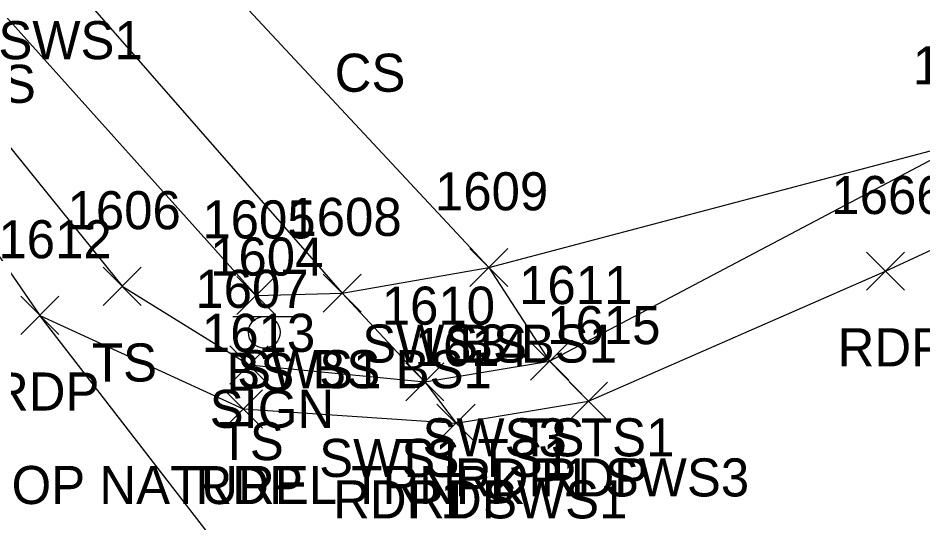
# Model space of a CAD drawing. Extents: x 1499292 to 1501024, y 534584 to 538043.
# Drawn here: x 1499887.83 to 1499935.33, y 537602.65 to 537629.17 of the extents above; entities that cross this region are included whole.
import ezdxf

# ---------------------------------------------------------------- set-up
doc = ezdxf.new("R2010")
doc.units = 0
for name, color, linetype in [('L_A', 7, 'Continuous'), ('L_I', 7, 'Continuous'), ('L_TIC', 7, 'Continuous'), ('LELB', 7, 'Continuous'), ('P_A', 7, 'Continuous'), ('P_I', 7, 'Continuous'), ('P_TIC', 7, 'Continuous'), ('PET', 7, 'Continuous'), ('R_A', 7, 'Continuous'), ('R_I', 7, 'Continuous'), ('R_TIC', 7, 'Continuous'), ('RSW', 7, 'Continuous'), ('S_A', 7, 'Continuous'), ('S_C', 7, 'Continuous'), ('S_I', 7, 'Continuous'), ('SSGN', 7, 'Continuous')]:
    doc.layers.add(name, color=color, linetype=linetype)

msp = doc.modelspace()

# ---------------------------------------------------------------- linework, layer by layer
at = {"layer": 'L_TIC'}
for points in [[(1499911.539, 537615.07), (1499913.539, 537617.07)], [(1499913.539, 537615.07), (1499911.539, 537617.07)], [(1499892.294, 537614.077), (1499894.294, 537616.077)], [(1499894.294, 537614.077), (1499892.294, 537616.077)], [(1499899.318, 537613.592), (1499901.318, 537615.592)], [(1499901.318, 537613.592), (1499899.318, 537615.592)], [(1499903.837, 537613.724), (1499905.837, 537615.724)], [(1499905.837, 537613.724), (1499903.837, 537615.724)], [(1499898.95, 537609.946), (1499900.95, 537611.946)], [(1499900.95, 537609.946), (1499898.95, 537611.946)], [(1499914.735, 537610.144), (1499916.735, 537612.144)], [(1499916.735, 537610.144), (1499914.735, 537612.144)], [(1499908.177, 537609.062), (1499910.177, 537611.062)], [(1499910.177, 537609.062), (1499908.177, 537611.062)]]:
    msp.add_lwpolyline(points, dxfattribs=at)
at = {"layer": 'LELB'}
for points in [[(1499875.628, 537635.389), (1499883.617, 537627.063), (1499893.294, 537615.077), (1499899.95, 537610.946), (1499909.177, 537610.062), (1499915.735, 537611.144), (1499937.582, 537622.682), (1499960.484, 537631.227), (1499993.025, 537642.588), (1500017.771, 537650.353)], [(1499878.067, 537642.108), (1499886.752, 537629.716), (1499900.318, 537614.592), (1499904.837, 537614.724), (1499912.539, 537616.07), (1499937.582, 537622.682)]]:
    msp.add_lwpolyline(points, dxfattribs=at)
at = {"layer": 'P_TIC'}
for points in [[(1499932.365, 537614.874), (1499934.365, 537616.874)], [(1499934.365, 537614.874), (1499932.365, 537616.874)], [(1499887.962, 537612.552), (1499889.962, 537614.552)], [(1499889.962, 537612.552), (1499887.962, 537614.552)], [(1499887.962, 537612.552), (1499889.962, 537614.552)], [(1499889.962, 537612.552), (1499887.962, 537614.552)], [(1499916.779, 537608.039), (1499918.779, 537610.039)], [(1499918.779, 537608.039), (1499916.779, 537610.039)], [(1499898.651, 537607.634), (1499900.651, 537609.634)], [(1499900.651, 537607.634), (1499898.651, 537609.634)], [(1499909.819, 537606.885), (1499911.819, 537608.885)], [(1499911.819, 537606.885), (1499909.819, 537608.885)]]:
    msp.add_lwpolyline(points, dxfattribs=at)
at = {"layer": 'PET'}
for points in [[(1499877.015, 537630.958), (1499888.962, 537613.552), (1499899.651, 537608.634), (1499910.819, 537607.885), (1499917.779, 537609.039), (1499933.365, 537615.874), (1499940.692, 537619.272), (1499961.056, 537627.699), (1499994.297, 537637.632), (1500011.746, 537642.235), (1500032.99, 537648.112)], [(1500289.781, 537338.292), (1500253.04, 537372.984), (1500224.755, 537395.044), (1500200.638, 537412.645), (1500169.786, 537433.283), (1500131.366, 537455.397), (1500082.939, 537477.86), (1500052.71, 537490.83), (1500028.687, 537501.079), (1500007.589, 537509.927), (1499989.795, 537518.651), (1499972.477, 537528.523), (1499952.084, 537542.885), (1499935.462, 537557.311), (1499909.986, 537586.349), (1499888.962, 537613.552)]]:
    msp.add_lwpolyline(points, dxfattribs=at)
at = {"layer": 'R_TIC'}
for points in [[(1499911.539, 537615.07), (1499913.539, 537617.07)], [(1499913.539, 537615.07), (1499911.539, 537617.07)], [(1499903.837, 537613.724), (1499905.837, 537615.724)], [(1499905.837, 537613.724), (1499903.837, 537615.724)], [(1499914.735, 537610.144), (1499916.735, 537612.144)], [(1499916.735, 537610.144), (1499914.735, 537612.144)], [(1499908.177, 537609.062), (1499910.177, 537611.062)], [(1499910.177, 537609.062), (1499908.177, 537611.062)], [(1499916.779, 537608.039), (1499918.779, 537610.039)], [(1499918.779, 537608.039), (1499916.779, 537610.039)], [(1499909.819, 537606.885), (1499911.819, 537608.885)], [(1499911.819, 537606.885), (1499909.819, 537608.885)]]:
    msp.add_lwpolyline(points, dxfattribs=at)
at = {"layer": 'RSW'}
for points in [[(1499852.884, 537673.411), (1499857.278, 537677.521), (1499874.596, 537657.81), (1499894.119, 537635.847), (1499912.539, 537616.07), (1499915.735, 537611.144), (1499917.779, 537609.039)], [(1499852.884, 537673.411), (1499870.266, 537654.325), (1499889.752, 537632.008), (1499904.837, 537614.724), (1499909.177, 537610.062), (1499910.819, 537607.885)]]:
    msp.add_lwpolyline(points, dxfattribs=at)
at = {"layer": 'SSGN'}
for p, q in [((1499899.101, 537613.494), (1499902.434, 537613.494)), ((1499900.748, 537612.661), (1499900.748, 537612.661))]:
    msp.add_line(p, q, dxfattribs=at)
msp.add_circle((1499900.748, 537612.661), 0.833, dxfattribs=at)

# ---------------------------------------------------------------- texts
at = {"layer": 'L_A'}
for s, p in [('CS', (1499904.446, 537625.298)), ('BS', (1499885.193, 537624.716)), ('BS', (1499910.98, 537611.07)), ('TS', (1499891.703, 537610.077)), ('BS', (1499898.759, 537609.592)), ('BS', (1499903.278, 537609.724)), ('TS', (1499914.145, 537606.144)), ('TS', (1499898.359, 537605.946)), ('TS', (1499907.586, 537605.062))]:
    msp.add_text(s, height=2, dxfattribs=at).set_placement(p)
at = {"layer": 'L_I'}
for s, p in [('1667', (1499934.794, 537625.682)), ('1667', (1499934.794, 537625.682)), ('1609', (1499909.712, 537619.07)), ('1606', (1499890.42, 537618.077)), ('1605', (1499897.499, 537617.592)), ('1608', (1499902.019, 537617.724)), ('1611', (1499914.129, 537614.144)), ('1607', (1499897.131, 537613.946)), ('1610', (1499906.917, 537613.062))]:
    msp.add_text(s, height=2, dxfattribs=at).set_placement(p)
at = {"layer": 'P_A'}
for p in [(1499930.853, 537610.874), (1499886.451, 537608.552), (1499886.451, 537608.552), (1499897.139, 537603.634), (1499915.267, 537604.039), (1499908.307, 537602.885)]:
    msp.add_text('RDP', height=2, dxfattribs=at).set_placement(p)
at = {"layer": 'P_I'}
for s, p in [('1666', (1499930.522, 537618.874)), ('1612', (1499886.789, 537616.552)), ('1612', (1499886.789, 537616.552)), ('1615', (1499915.605, 537612.039)), ('1613', (1499897.478, 537611.634)), ('1614', (1499908.645, 537610.885))]:
    msp.add_text(s, height=2, dxfattribs=at).set_placement(p)
at = {"layer": 'R_A'}
for s, p in [('SWS1', (1499886.791, 537627.008)), ('SWS3 BS1', (1499905.893, 537611.07)), ('SWS1 BS1', (1499899.326, 537609.724)), ('SWS3 TS1', (1499909.058, 537606.144)), ('SWS1 TS1', (1499903.633, 537605.062)), ('RDP1 SWS3', (1499910.755, 537604.039)), ('RDP1 SWS1', (1499904.362, 537602.885))]:
    msp.add_text(s, height=2, dxfattribs=at).set_placement(p)
at = {"layer": 'R_I'}
for s, p in [('1609', (1499909.712, 537619.07)), ('1608', (1499902.019, 537617.724)), ('1611', (1499914.129, 537614.144)), ('1610', (1499906.917, 537613.062)), ('1615', (1499915.605, 537612.039)), ('1614', (1499908.645, 537610.885))]:
    msp.add_text(s, height=2, dxfattribs=at).set_placement(p)
at = {"layer": 'S_A'}
msp.add_text('SIGN', height=2, dxfattribs=at).set_placement((1499897.886, 537607.641))
at = {"layer": 'S_C'}
msp.add_text('STOP NATUREL TRNPK', height=2, dxfattribs=at).set_placement((1499884.067, 537603.641))
at = {"layer": 'S_I'}
msp.add_text('1604', height=2, dxfattribs=at).set_placement((1499897.909, 537615.641))

doc.saveas('drawing.dxf')
